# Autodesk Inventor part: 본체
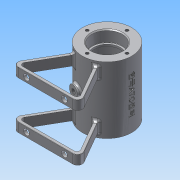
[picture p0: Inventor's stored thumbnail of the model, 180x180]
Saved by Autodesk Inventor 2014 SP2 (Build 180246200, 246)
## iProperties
Created: 2016-03
Part Number: 본체
Material: 알루미늄 6061
Document SubType Name: Modeling
Designer: 703
Density: 2.71 g/cm^3
Appearance: 알루미늄 - 평지
Mass: 209.91 g
Surface Area: 331.029 cm^2
Volume: 77.4574 cm^3
Author: 703
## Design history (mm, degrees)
sketch "스케치1"
  geometry: C1 r 26 at (0, 0); 1 further point
  constraints: 1 centre point, 1 coincident
  dimensions: "d0" = 52 diameter of C1
extrude "돌출1" new body sketch "스케치1" stored distance "d1" = 70; taper "d2" = 0 deg
sketch "스케치2"
  geometry: C1 r 21 at (0, 0); 1 further point
  constraints: 1 centre point, 1 coincident
  dimensions: "d3" = 42 diameter of C1
extrude "돌출2" cut sketch "스케치2" stored distance "d4" = 42; taper "d5" = 0 deg
hole "구멍1" diameter "d8" = 32; stored, may be unused: countersink angle "d12" = 90 deg, drill point angle "d14" = 0 deg; dims "d6" = 10, "d7" = 10, "d9" = 6, "d10" = 4, "d11" = 2, "d13" = 12
hole "구멍2" diameter "d17" = 28; stored, may be unused: countersink angle "d21" = 90 deg, drill point angle "d23" = 0 deg; dims "d15" = 10, "d16" = 10, "d18" = 6, "d19" = 4, "d20" = 2, "d22" = 2
hole "구멍3" diameter "d26" = 32; stored, may be unused: countersink angle "d30" = 90 deg, drill point angle "d32" = 0 deg; dims "d24" = 10, "d25" = 10, "d27" = 6, "d28" = 4, "d29" = 2, "d31" = 12
hole "구멍4" diameter "d35" = 28; stored, may be unused: countersink angle "d39" = 90 deg, drill point angle "d41" = 0 deg; dims "d33" = 10, "d34" = 10, "d36" = 6, "d37" = 4, "d38" = 2, "d40" = 2
node "작업 평면1"
sketch "스케치5"
  geometry: L1 (0, 0)-(0, -65); L2 (-13, -22.517)-(-37.528, -65); L3 (0, -65)-(-37.528, -65); L4 (13, -22.517)-(37.528, -65); L5 (0, -65)-(37.528, -65); L6 (10.315, -23.866)-(32.332, -62); L7 (32.332, -62)-(0, -62); L8 (-10.315, -23.866)-(-32.332, -62); L9 (-32.332, -62)-(0, -62); C1 r 16 at (0, 0) reference; A1 r 26 centre (0, 0) between (-13, -22.517) and (13, -22.517); 3 further points
  constraints: 18 end point, 4 point on circle, 4 symmetric about line, 2 point on line, 1 centre point, 1 coincident, 1 perpendicular, 1 vertical, 2 other
  dimensions: "d45" = 65 distance of L1.start L1.end; "d46" = 30 deg angle of L1 L2; "d47" = 42.48334 vertical distance of L2.end L2.start; "d48" = 3 distance between parallel lines of L4 L6; "d50" = 3 distance between parallel lines of L5 L7
extrude "돌출3" join sketch "스케치5" distance "d51" = 10; taper "d52" = 0 deg
node "작업 평면4"
sketch "스케치9"
  geometry: C1 r 5 at (0, 0); 1 further point
  constraints: 1 centre point, 1 coincident
  dimensions: "d71" = 10 diameter of C1
extrude "돌출5" join sketch "스케치9" stored distance "d72" = 3; taper "d73" = 0 deg
hole "구멍6" diameter "d76" = 5.188; stored, may be unused: countersink angle "d80" = 90 deg, drill point angle "d82" = 0 deg; dims "d77" = 10, "d78" = 4, "d79" = 2, "d81" = 10, "d85" = 10, "d86" = 10
sketch "스케치14"
  geometry: L1 (0, 0)-(0, -65); L2 (-37.528, -65)-(37.528, -65) reference; L3 (0, 0)-(-7.506, -28.012); L4 (-7.506, -28.012)-(-1.71, -29.565); L5 (-1.71, -29.565)-(-0.752, -25.989); L6 (-0.752, -25.989)-(-6.548, -24.436); C1 r 16 at (0, 0) reference; 2 further points
  constraints: 10 end point, 3 perpendicular, 1 midpoint, 1 point on line, 2 other
  dimensions: "d104" = 15 deg angle of L1 L3; "d105" = 29 distance of point (0, 0) L3.end; "d106" = 6 distance of L3.end L4.end
fillet "모깎기1" dims "d117" = 5
sketch "스케치15"
  geometry: L1 (64.663, 0)-(0, 0) reference; C1 r 3 at (12.332, -5); 1 further point
  constraints: 1 centre point
  dimensions: "d118" = 5 distance from line of L1 C1.centre; "d119" = 20 horizontal distance of point (32.332, 20) C1.centre; "d120" = 6 diameter of C1
extrude "돌출6" cut sketch "스케치15" stored distance "d121" = 3; taper "d122" = 0 deg
sketch "스케치16" dims "d123" = 42
  geometry: C1 r 26 at (0, 0) reference; 2 further points
  constraints: 2 vertical alignment, 1 coincident, 2 other
hole "구멍9" sketch "스케치16" at (0, 21) diameter "d124" = 3.242; stored, may be unused: countersink angle "d128" = 90 deg, drill point angle "d130" = 118 deg; dims "d125" = 8, "d126" = 4, "d127" = 2, "d129" = 10
fillet "모깎기2" dims "d134" = 3
fillet "모깎기3" dims "d135" = 0.3
chamfer "모따기1" distance "d136" = 1; stored, may be unused: second distance "d137" = 2, angle "d138" = 45 deg
node "작업 평면5"
sketch "스케치17"
  geometry: L1 (26, 35)-(-26, 35) reference; L2 (26, -35)-(26, 35) reference; 2 further points
  constraints: 1 other
  dimensions: "d139" = 35 distance from line of L1 point (0, 0); "d140" = 26 distance from line of L2 point (0, 0)
feature "엠보싱1" sketch "스케치17" dims "d0" = 52, "d33" = 10, "d141" = 0.5, "d142" = 0
fillet "모깎기4" dims "d143" = 3
fillet "모깎기5" dims "d144" = 0.3
fillet "모깎기6" dims "d145" = 3
revolve "회전3" stored, may be unused: angle "d146" = 90 deg
hole "구멍10" diameter "d149" = 5.188; stored, may be unused: countersink angle "d153" = 90 deg, drill point angle "d155" = 118 deg; dims "d150" = 10, "d151" = 4, "d152" = 2, "d154" = 10, "d156" = 10, "d157" = 10
fillet "모깎기7" dims "d158" = 2
node "솔리드1"
mirror "대칭1"
mirror "대칭2"
mirror "대칭3"
pattern_circular "원형 패턴1" dims angle "d132" = 360 deg
mirror "대칭4"
node "투영된 루프1"
other parameters: "d70" = 29
